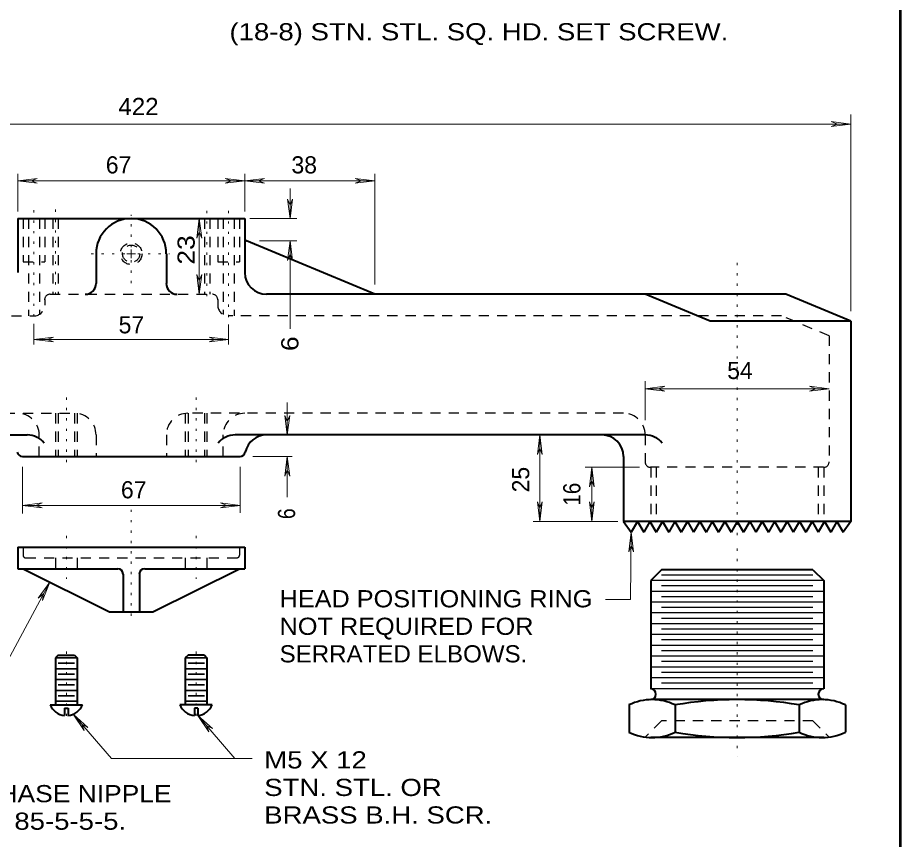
# Model space of a CAD drawing. Extents: x 312583 to 312854, y 144419 to 144597.
# Drawn here: x 312651.22 to 312690.31, y 144522.02 to 144558.42 of the extents above; entities that cross this region are included whole.
import ezdxf

# ---------------------------------------------------------------- set-up
doc = ezdxf.new("R2010")
doc.units = 0
doc.header["$LTSCALE"] = 0.3
doc.linetypes.add('DOTTED', pattern=[1.5, 0.3, -1.2])
doc.linetypes.add('SHORT_DASHED', pattern=[2.7, 1.5, -1.2])
doc.layers.add('1', color=7, linetype='Continuous', lineweight=40)
doc.layers.add('2', color=7, linetype='Continuous', lineweight=13)

msp = doc.modelspace()

# ---------------------------------------------------------------- linework, layer by layer
at = {"layer": '1', "lineweight": 53}
msp.add_line((312690.3095, 144476.2913), (312690.3095, 144585.0846), dxfattribs=at)
at = {"layer": '1', "linetype": 'DOTTED', "lineweight": 13}
for p, q in [((312651.9371, 144549.8912), (312651.9371, 144544.8619)), ((312652.8954, 144549.9219), (312652.8954, 144545.8049)), ((312659.6037, 144549.8605), (312659.6037, 144545.8049)), ((312660.5621, 144549.8605), (312660.5621, 144544.8312)), ((312683.0867, 144547.5605), (312683.0867, 144535.1559)), ((312653.3784, 144541.5959), (312653.3784, 144538.3989)), ((312659.1284, 144541.5959), (312659.1284, 144538.3989)), ((312656.2534, 144536.6279), (312656.2534, 144531.5679)), ((312653.3784, 144535.4625), (312653.3784, 144533.5612)), ((312659.1284, 144535.4625), (312659.1284, 144533.5612)), ((312683.0867, 144534.9105), (312683.0867, 144525.7029)), ((312653.3784, 144530.3489), (312653.3784, 144527.2899)), ((312659.1284, 144530.3489), (312659.1284, 144527.2899))]:
    msp.add_line(p, q, dxfattribs=at)
at = {"layer": '1'}
for p, q in [((312651.2241, 144549.5232), (312651.2241, 144547.1312)), ((312651.2241, 144549.5232), (312661.2827, 144549.5232)), ((312661.2827, 144549.5232), (312661.2827, 144547.1312)), ((312667.0327, 144546.1729), (312661.3594, 144548.5342)), ((312654.6971, 144547.9669), (312654.6971, 144546.6482)), ((312657.8097, 144547.9669), (312657.8097, 144546.6482)), ((312685.2411, 144546.1729), (312662.2411, 144546.1729)), ((312681.8831, 144544.9769), (312679.0081, 144546.1729)), ((312688.1161, 144544.9769), (312685.2411, 144546.1729)), ((312688.1161, 144544.9769), (312681.8831, 144544.9769)), ((312633.4911, 144539.9399), (312651.6457, 144539.9399)), ((312679.0081, 144539.9399), (312660.8534, 144539.9399)), ((312651.4387, 144538.9815), (312661.0681, 144538.9815)), ((312678.0497, 144538.9815), (312678.0497, 144536.1065)), ((312678.0497, 144536.1065), (312678.3947, 144535.6312)), ((312678.6707, 144536.1065), (312678.3947, 144535.6312)), ((312678.6707, 144536.1065), (312678.9467, 144535.6312)), ((312679.2227, 144536.1065), (312678.9467, 144535.6312)), ((312679.2227, 144536.1065), (312679.4987, 144535.6312)), ((312679.7747, 144536.1065), (312679.4987, 144535.6312)), ((312679.7747, 144536.1065), (312680.0507, 144535.6312)), ((312680.3267, 144536.1065), (312680.0507, 144535.6312)), ((312680.3267, 144536.1065), (312680.6027, 144535.6312)), ((312680.8787, 144536.1065), (312680.6027, 144535.6312)), ((312680.8787, 144536.1065), (312681.1547, 144535.6312)), ((312681.4307, 144536.1065), (312681.1547, 144535.6312)), ((312681.4307, 144536.1065), (312681.7067, 144535.6312)), ((312681.9827, 144536.1065), (312681.7067, 144535.6312)), ((312681.9827, 144536.1065), (312682.2587, 144535.6312)), ((312682.5347, 144536.1065), (312682.2587, 144535.6312)), ((312682.5347, 144536.1065), (312682.8107, 144535.6312)), ((312683.0867, 144536.1065), (312682.8107, 144535.6312)), ((312683.0867, 144536.1065), (312683.3627, 144535.6312)), ((312683.6387, 144536.1065), (312683.3627, 144535.6312)), ((312683.6387, 144536.1065), (312683.9147, 144535.6312)), ((312684.1907, 144536.1065), (312683.9147, 144535.6312)), ((312684.1907, 144536.1065), (312684.4667, 144535.6312)), ((312684.7427, 144536.1065), (312684.4667, 144535.6312)), ((312684.7427, 144536.1065), (312685.0187, 144535.6312)), ((312685.2947, 144536.1065), (312685.0187, 144535.6312)), ((312685.2947, 144536.1065), (312685.5707, 144535.6312)), ((312685.8467, 144536.1065), (312685.5707, 144535.6312)), ((312685.8467, 144536.1065), (312686.1227, 144535.6312)), ((312686.3987, 144536.1065), (312686.1227, 144535.6312)), ((312686.3987, 144536.1065), (312686.6747, 144535.6312)), ((312686.9507, 144536.1065), (312686.6747, 144535.6312)), ((312686.9507, 144536.1065), (312687.2267, 144535.6312)), ((312687.5027, 144536.1065), (312687.2267, 144535.6312)), ((312687.5027, 144536.1065), (312687.7787, 144535.6312)), ((312688.1161, 144536.1065), (312687.7787, 144535.6312)), ((312651.2241, 144534.9719), (312661.2827, 144534.9719)), ((312651.2241, 144534.9719), (312651.2241, 144534.0135)), ((312661.2827, 144534.9719), (312661.2827, 144534.0135)), ((312651.2241, 144534.0135), (312655.6554, 144534.0135)), ((312651.4617, 144534.0135), (312655.2951, 144532.0969)), ((312655.8931, 144533.7759), (312655.8931, 144532.0969)), ((312656.6137, 144533.7759), (312656.6137, 144532.0969)), ((312656.8514, 144534.0135), (312661.2827, 144534.0135)), ((312657.2117, 144532.0969), (312661.0451, 144534.0135)), ((312679.7287, 144533.9675), (312679.2534, 144533.4845)), ((312686.4371, 144533.9675), (312679.7287, 144533.9675)), ((312686.4371, 144533.9675), (312686.9201, 144533.4845)), ((312679.2534, 144533.4845), (312679.2534, 144528.6929)), ((312686.9201, 144533.4845), (312686.9201, 144528.6929)), ((312655.2951, 144532.0969), (312657.2117, 144532.0969)), ((312653.0181, 144530.1802), (312652.8954, 144530.0652)), ((312653.0181, 144530.1802), (312653.7387, 144530.1802)), ((312653.7387, 144530.1802), (312653.8537, 144530.0652)), ((312658.7681, 144530.1802), (312658.6454, 144530.0652)), ((312659.4887, 144530.1802), (312658.7681, 144530.1802)), ((312659.4887, 144530.1802), (312659.6037, 144530.0652)), ((312652.8954, 144530.0652), (312652.8954, 144527.9875)), ((312653.8537, 144530.0652), (312653.8537, 144527.9875)), ((312658.6454, 144530.0652), (312658.6454, 144527.9875)), ((312659.6037, 144530.0652), (312659.6037, 144527.9875)), ((312686.9201, 144528.2175), (312679.2534, 144528.2175)), ((312652.6577, 144527.9875), (312654.0991, 144527.9875)), ((312653.3017, 144527.8419), (312653.3017, 144527.5122)), ((312653.3017, 144527.8419), (312653.4551, 144527.8419)), ((312653.4551, 144527.8419), (312653.4551, 144527.5122)), ((312659.8414, 144527.9875), (312658.4077, 144527.9875)), ((312659.0517, 144527.8419), (312659.0517, 144527.5122)), ((312659.2051, 144527.8419), (312659.0517, 144527.8419)), ((312659.2051, 144527.8419), (312659.2051, 144527.5122)), ((312678.2951, 144527.9799), (312678.2951, 144526.7762)), ((312680.3344, 144527.9799), (312680.3344, 144526.7762)), ((312685.8314, 144527.9799), (312685.8314, 144526.7762)), ((312687.8784, 144527.9799), (312687.8784, 144526.7762)), ((312686.9201, 144526.5385), (312679.2534, 144526.5385))]:
    msp.add_line(p, q, dxfattribs=at)
at = {"layer": '1', "linetype": 'SHORT_DASHED', "lineweight": 25}
for p, q in [((312651.6994, 144549.5232), (312651.6994, 144545.2145)), ((312652.1824, 144549.5232), (312652.1824, 144545.2759)), ((312652.4201, 144549.5232), (312652.4201, 144547.6065)), ((312652.7804, 144549.5232), (312652.7804, 144546.1729)), ((312653.0181, 144549.5232), (312653.0181, 144546.1729)), ((312659.4887, 144549.5232), (312659.4887, 144546.1729)), ((312659.7264, 144549.5232), (312659.7264, 144546.1729)), ((312660.0867, 144549.5232), (312660.0867, 144547.6065)), ((312660.3244, 144549.5232), (312660.3244, 144545.2759)), ((312660.8074, 144549.5232), (312660.8074, 144545.2145)), ((312661.0451, 144549.5232), (312661.0451, 144547.6065)), ((312660.0867, 144547.6065), (312661.0451, 144547.6065)), ((312652.6577, 144546.1729), (312659.8491, 144546.1729)), ((312652.4201, 144545.9352), (312652.4201, 144545.6899)), ((312660.0867, 144545.9352), (312660.0867, 144545.6899)), ((312627.4574, 144545.2145), (312651.9371, 144545.2145)), ((312685.0494, 144545.2145), (312660.5621, 144545.2145)), ((312687.1577, 144544.3329), (312685.0494, 144545.2145)), ((312687.1577, 144544.3329), (312687.1577, 144538.7439)), ((312634.4494, 144540.8982), (312653.7387, 144540.8982)), ((312652.8954, 144540.8982), (312652.8954, 144538.9815)), ((312653.0181, 144540.8982), (312653.0181, 144538.9815)), ((312653.7387, 144540.8982), (312653.7387, 144538.9815)), ((312653.8537, 144540.8982), (312653.8537, 144538.9815)), ((312658.6454, 144540.8982), (312658.6454, 144538.9815)), ((312678.0497, 144540.8982), (312658.7681, 144540.8982)), ((312658.7681, 144540.8982), (312658.7681, 144538.9815)), ((312659.4887, 144540.8982), (312659.4887, 144538.9815)), ((312659.6037, 144540.8982), (312659.6037, 144538.9815)), ((312652.1747, 144538.9815), (312652.1747, 144539.9399)), ((312654.6971, 144539.9399), (312654.6971, 144538.9815)), ((312657.8097, 144539.9399), (312657.8097, 144538.9815)), ((312660.3244, 144538.9815), (312660.3244, 144539.9399)), ((312679.0081, 144539.9399), (312679.0081, 144538.7439)), ((312686.9124, 144538.5062), (312679.2457, 144538.5062)), ((312679.2534, 144538.5062), (312679.2534, 144536.1065)), ((312679.4911, 144538.5062), (312679.4911, 144536.1065)), ((312686.6747, 144538.5062), (312686.6747, 144536.1065)), ((312686.9201, 144538.5062), (312686.9201, 144536.1065)), ((312651.4617, 144534.9719), (312651.4617, 144534.6115)), ((312661.0451, 144534.9719), (312661.0451, 144534.6115)), ((312651.5844, 144534.4965), (312660.9301, 144534.4965)), ((312652.8954, 144534.4965), (312652.8954, 144534.0135)), ((312653.8537, 144534.4965), (312653.8537, 144534.0135)), ((312658.6454, 144534.4965), (312658.6454, 144534.0135)), ((312659.6037, 144534.4965), (312659.6037, 144534.0135)), ((312679.7287, 144527.2745), (312679.0157, 144526.5539)), ((312686.4371, 144527.2745), (312679.7287, 144527.2745)), ((312686.4371, 144527.2745), (312687.1577, 144526.5539))]:
    msp.add_line(p, q, dxfattribs=at)
at = {"layer": '1', "lineweight": 25}
for p, q in [((312686.4371, 144533.7299), (312679.7287, 144533.7299)), ((312686.9201, 144533.4845), (312679.2534, 144533.4845)), ((312686.4371, 144533.2469), (312679.7287, 144533.2469)), ((312686.9201, 144533.0092), (312679.2534, 144533.0092)), ((312686.9201, 144532.5262), (312679.2534, 144532.5262)), ((312686.4371, 144532.7715), (312679.7287, 144532.7715)), ((312686.4371, 144532.2885), (312679.7287, 144532.2885)), ((312686.9201, 144532.0509), (312679.2534, 144532.0509)), ((312686.4371, 144531.8132), (312679.7287, 144531.8132)), ((312686.9201, 144531.5679), (312679.2534, 144531.5679)), ((312686.4371, 144531.3302), (312679.7287, 144531.3302)), ((312686.9201, 144531.0925), (312679.2534, 144531.0925)), ((312686.9201, 144530.6095), (312679.2534, 144530.6095)), ((312686.4371, 144530.8549), (312679.7287, 144530.8549)), ((312686.9201, 144530.1342), (312679.2534, 144530.1342)), ((312686.4371, 144530.3719), (312679.7287, 144530.3719)), ((312686.4371, 144529.8965), (312679.7287, 144529.8965)), ((312686.9201, 144529.6512), (312679.2534, 144529.6512)), ((312686.4371, 144529.4135), (312679.7287, 144529.4135)), ((312686.9201, 144529.1759), (312679.2534, 144529.1759)), ((312686.9201, 144528.6929), (312679.2534, 144528.6929)), ((312686.4371, 144528.9382), (312679.7287, 144528.9382))]:
    msp.add_line(p, q, dxfattribs=at)
at = {"layer": '1', "lineweight": 35}
for p, q in [((312652.8954, 144530.0652), (312653.8537, 144530.0652)), ((312653.0181, 144529.8275), (312653.7387, 144529.8275)), ((312659.6037, 144530.0652), (312658.6454, 144530.0652)), ((312658.7681, 144529.8275), (312659.4887, 144529.8275)), ((312652.8954, 144529.5822), (312653.8537, 144529.5822)), ((312653.0181, 144529.3445), (312653.7387, 144529.3445)), ((312658.6454, 144529.5822), (312659.6037, 144529.5822)), ((312658.7681, 144529.3445), (312659.4887, 144529.3445)), ((312652.8954, 144529.1069), (312653.8537, 144529.1069)), ((312658.6454, 144529.1069), (312659.6037, 144529.1069)), ((312652.8954, 144528.6239), (312653.8537, 144528.6239)), ((312653.0181, 144528.8692), (312653.7387, 144528.8692)), ((312658.6454, 144528.6239), (312659.6037, 144528.6239)), ((312658.7681, 144528.8692), (312659.4887, 144528.8692)), ((312653.0181, 144528.3862), (312653.7387, 144528.3862)), ((312658.7681, 144528.3862), (312659.4887, 144528.3862)), ((312652.8954, 144528.1485), (312653.8537, 144528.1485)), ((312658.6454, 144528.1485), (312659.6037, 144528.1485))]:
    msp.add_line(p, q, dxfattribs=at)
at = {"layer": '1', "linetype": 'SHORT_DASHED', "lineweight": 25}
msp.add_lwpolyline([(312651.4617, 144549.5232), (312651.4617, 144547.6065), (312652.4201, 144547.6065)], dxfattribs=at)
at = {"layer": '1'}
msp.add_lwpolyline([(312688.1161, 144544.9769), (312688.1161, 144536.1065), (312678.0497, 144536.1065)], dxfattribs=at)
at = {"layer": '1', "linetype": 'SHORT_DASHED', "lineweight": 25}
for radius in [0.4792, 0.3833]:
    msp.add_circle((312656.2496, 144547.9669), radius, dxfattribs=at)
at = {"layer": '1'}
for centre, radius, start, end in [((312656.2496, 144547.9669), 1.5563, 0, 180), ((312661.4025, 144548.6447), 0.1198, 180, 247.38014), ((312662.2411, 144547.1274), 0.9583, 180, 270), ((312654.2141, 144546.6482), 0.4792, 270, 0), ((312658.2851, 144546.6482), 0.4792, 180, 270), ((312651.6457, 144538.9815), 0.9583, 38.26143, 90), ((312660.8534, 144538.9815), 0.9583, 90, 141.73857), ((312662.2411, 144538.9815), 0.9583, 90, 168.46304), ((312677.0914, 144538.9815), 0.9583, 0, 90), ((312679.0081, 144538.9815), 0.9583, 38.26143, 90), ((312651.4356, 144539.2211), 0.2396, 191.53696, 270), ((312661.0674, 144539.2211), 0.2396, 270, 348.46304), ((312655.6497, 144533.774), 0.2396, 0, 90), ((312656.8495, 144533.774), 0.2396, 90, 180), ((312679.2496, 144528.4514), 0.2396, 270, 90), ((312686.9162, 144528.4514), 0.2396, 90, 270), ((312679.3128, 144525.8993), 2.3144, 63.80664, 116.19336), ((312683.081, 144512.1802), 16.0335, 80.12254, 99.87746), ((312686.853, 144525.8993), 2.3144, 63.80664, 116.19336), ((312653.3765, 144528.287), 0.7786, 202.61961, 264.2087), ((312653.3765, 144528.287), 0.7786, 275.51058, 337.3804), ((312659.1227, 144528.287), 0.7786, 202.6196, 264.48942), ((312659.1227, 144528.287), 0.7786, 275.7913, 337.38039), ((312679.3128, 144528.8491), 2.3144, 243.80664, 296.19336), ((312683.081, 144542.5682), 16.0335, 260.12254, 279.87746), ((312686.853, 144528.8491), 2.3144, 243.80664, 296.19336)]:
    msp.add_arc(centre, radius, start, end, dxfattribs=at)
at = {"layer": '1', "linetype": 'SHORT_DASHED', "lineweight": 25}
for centre, radius, start, end in [((312652.6558, 144545.9294), 0.2396, 90, 180), ((312659.8433, 144545.9294), 0.2396, 0, 90), ((312651.9371, 144545.6899), 0.4792, 270, 0), ((312660.5621, 144545.6899), 0.4792, 180, 270), ((312651.2164, 144539.9399), 0.9583, 0, 90), ((312653.7349, 144539.9399), 0.9583, 0, 90), ((312658.7642, 144539.9399), 0.9583, 90, 180), ((312661.2827, 144539.9399), 0.9583, 90, 180), ((312678.0497, 144539.9399), 0.9583, 0, 90), ((312679.2477, 144538.7419), 0.2396, 180, 270), ((312686.9143, 144538.7419), 0.2396, 270, 0), ((312651.5815, 144534.6125), 0.1198, 180, 270), ((312660.9253, 144534.6125), 0.1198, 270, 0)]:
    msp.add_arc(centre, radius, start, end, dxfattribs=at)
at = {"layer": '2'}
for p, q in [((312688.1161, 144545.4215), (312688.1161, 144554.1309)), ((312624.3907, 144553.7092), (312688.1161, 144553.7092)), ((312687.2497, 144553.8165), (312687.5257, 144553.7092)), ((312688.1161, 144553.7092), (312687.2497, 144553.8165)), ((312687.2497, 144553.6019), (312687.5257, 144553.7092)), ((312688.1161, 144553.7092), (312687.2497, 144553.6019)), ((312651.2241, 144549.8375), (312651.2241, 144551.5089)), ((312651.2241, 144551.1945), (312652.0904, 144551.3019)), ((312652.0904, 144551.3019), (312651.8144, 144551.1945)), ((312660.4164, 144551.3019), (312660.6924, 144551.1945)), ((312661.2827, 144551.1945), (312660.4164, 144551.3019)), ((312661.2827, 144549.8375), (312661.2827, 144551.5089)), ((312661.2827, 144551.1945), (312662.1491, 144551.3019)), ((312662.1491, 144551.3019), (312661.8731, 144551.1945)), ((312666.1664, 144551.3019), (312666.4424, 144551.1945)), ((312667.0327, 144551.1945), (312666.1664, 144551.3019)), ((312667.0327, 144546.6022), (312667.0327, 144551.5089)), ((312651.2241, 144551.1945), (312652.0904, 144551.0872)), ((312652.0904, 144551.0872), (312651.8144, 144551.1945)), ((312660.4164, 144551.0872), (312660.6924, 144551.1945)), ((312661.2827, 144551.1945), (312660.4164, 144551.0872)), ((312661.2827, 144551.1945), (312662.1491, 144551.0872)), ((312662.1491, 144551.0872), (312661.8731, 144551.1945)), ((312663.2837, 144549.5232), (312663.2837, 144550.8572)), ((312666.1664, 144551.0872), (312666.4424, 144551.1945)), ((312667.0327, 144551.1945), (312666.1664, 144551.0872)), ((312663.1764, 144550.3895), (312663.2837, 144550.1135)), ((312663.2837, 144549.5232), (312663.1764, 144550.3895)), ((312663.3911, 144550.3895), (312663.2837, 144550.1135)), ((312663.2837, 144549.5232), (312663.3911, 144550.3895)), ((312659.2664, 144549.5232), (312659.1591, 144548.6569)), ((312659.2664, 144546.1729), (312659.2664, 144549.5232)), ((312659.2664, 144549.5232), (312659.3737, 144548.6569)), ((312661.4974, 144549.5232), (312663.5827, 144549.5232)), ((312659.1591, 144548.6569), (312659.2664, 144548.9329)), ((312659.3737, 144548.6569), (312659.2664, 144548.9329)), ((312661.9344, 144548.5342), (312663.5827, 144548.5342)), ((312663.2837, 144548.5342), (312663.1764, 144547.6679)), ((312663.2837, 144544.6395), (312663.2837, 144548.5342)), ((312663.2837, 144548.5342), (312663.3911, 144547.6679)), ((312656.2534, 144547.9669), (312656.2534, 144548.1585)), ((312656.2534, 144547.9669), (312656.0617, 144547.9669)), ((312656.2534, 144547.9669), (312656.2534, 144547.7752)), ((312656.2534, 144547.9669), (312656.4451, 144547.9669)), ((312663.1764, 144547.6679), (312663.2837, 144547.9439)), ((312663.3911, 144547.6679), (312663.2837, 144547.9439)), ((312659.1591, 144547.0392), (312659.2664, 144546.7632)), ((312659.2664, 144546.1729), (312659.1591, 144547.0392)), ((312659.3737, 144547.0392), (312659.2664, 144546.7632)), ((312659.2664, 144546.1729), (312659.3737, 144547.0392)), ((312651.9371, 144544.8619), (312651.9371, 144543.9419)), ((312660.5621, 144544.8312), (312660.5621, 144543.9419)), ((312651.9371, 144544.1642), (312652.8034, 144544.2715)), ((312652.8034, 144544.2715), (312652.5274, 144544.1642)), ((312659.6957, 144544.2715), (312659.9717, 144544.1642)), ((312660.5621, 144544.1642), (312659.6957, 144544.2715)), ((312651.9371, 144544.1642), (312660.5621, 144544.1642)), ((312651.9371, 144544.1642), (312652.8034, 144544.0569)), ((312652.8034, 144544.0569), (312652.5274, 144544.1642)), ((312659.6957, 144544.0569), (312659.9717, 144544.1642)), ((312660.5621, 144544.1642), (312659.6957, 144544.0569)), ((312679.0081, 144540.5992), (312679.0081, 144542.3242)), ((312679.0081, 144541.9869), (312679.8744, 144542.0942)), ((312687.1577, 144541.9869), (312679.0081, 144541.9869)), ((312679.0081, 144541.9869), (312679.8744, 144541.8795)), ((312679.8744, 144542.0942), (312679.5984, 144541.9869)), ((312679.8744, 144541.8795), (312679.5984, 144541.9869)), ((312686.2914, 144542.0942), (312686.5674, 144541.9869)), ((312687.1577, 144541.9869), (312686.2914, 144542.0942)), ((312686.2914, 144541.8795), (312686.5674, 144541.9869)), ((312687.1577, 144541.9869), (312686.2914, 144541.8795)), ((312663.1611, 144541.3812), (312663.1611, 144539.9399)), ((312663.0537, 144540.8062), (312663.1611, 144540.5302)), ((312663.1611, 144539.9399), (312663.0537, 144540.8062)), ((312663.2684, 144540.8062), (312663.1611, 144540.5302)), ((312663.1611, 144539.9399), (312663.2684, 144540.8062)), ((312674.3467, 144539.9399), (312674.2394, 144539.0735)), ((312674.3467, 144536.1065), (312674.3467, 144539.9399)), ((312674.3467, 144539.9399), (312674.4541, 144539.0735)), ((312674.2394, 144539.0735), (312674.3467, 144539.3495)), ((312674.4541, 144539.0735), (312674.3467, 144539.3495)), ((312661.6354, 144538.9815), (312663.3757, 144538.9815)), ((312663.1611, 144538.9815), (312663.0537, 144538.1152)), ((312663.1611, 144538.9815), (312663.1611, 144537.1875)), ((312663.1611, 144538.9815), (312663.2684, 144538.1152)), ((312651.4387, 144538.5292), (312651.4387, 144536.4515)), ((312661.0681, 144538.5292), (312661.0681, 144536.4899)), ((312663.0537, 144538.1152), (312663.1611, 144538.3912)), ((312663.2684, 144538.1152), (312663.1611, 144538.3912)), ((312678.7627, 144538.5062), (312676.3554, 144538.5062)), ((312676.6467, 144538.5062), (312676.5394, 144537.6399)), ((312676.6467, 144536.1065), (312676.6467, 144538.5062)), ((312676.6467, 144538.5062), (312676.7541, 144537.6399)), ((312676.5394, 144537.6399), (312676.6467, 144537.9159)), ((312676.7541, 144537.6399), (312676.6467, 144537.9159)), ((312651.4387, 144536.8195), (312652.3051, 144536.9269)), ((312651.4387, 144536.8195), (312661.0681, 144536.8195)), ((312651.4387, 144536.8195), (312652.3051, 144536.7122)), ((312652.3051, 144536.9269), (312652.0291, 144536.8195)), ((312652.3051, 144536.7122), (312652.0291, 144536.8195)), ((312660.2017, 144536.9269), (312660.4777, 144536.8195)), ((312661.0681, 144536.8195), (312660.2017, 144536.9269)), ((312660.2017, 144536.7122), (312660.4777, 144536.8195)), ((312661.0681, 144536.8195), (312660.2017, 144536.7122)), ((312674.2394, 144536.9729), (312674.3467, 144536.6969)), ((312674.3467, 144536.1065), (312674.2394, 144536.9729)), ((312674.4541, 144536.9729), (312674.3467, 144536.6969)), ((312674.3467, 144536.1065), (312674.4541, 144536.9729)), ((312676.5394, 144536.9729), (312676.6467, 144536.6969)), ((312676.6467, 144536.1065), (312676.5394, 144536.9729)), ((312676.7541, 144536.9729), (312676.6467, 144536.6969)), ((312676.6467, 144536.1065), (312676.7541, 144536.9729)), ((312677.8044, 144536.1065), (312674.0554, 144536.1065)), ((312678.3947, 144535.6312), (312678.2797, 144534.7649)), ((312678.3947, 144535.6312), (312678.4944, 144534.7649)), ((312678.2797, 144534.7649), (312678.3871, 144535.0409)), ((312678.4944, 144534.7649), (312678.3871, 144535.0409)), ((312652.6424, 144533.4232), (312652.1364, 144532.7102)), ((312652.6424, 144533.4232), (312652.3281, 144532.6105)), ((312652.1364, 144532.7102), (312652.3664, 144532.9019)), ((312652.3281, 144532.6105), (312652.3664, 144532.9019)), ((312653.6774, 144527.5735), (312654.1604, 144526.8452)), ((312653.6774, 144527.5735), (312654.3291, 144526.9832)), ((312659.2051, 144527.5122), (312660.8457, 144525.6109)), ((312659.2051, 144527.5122), (312659.6881, 144526.7915)), ((312659.2051, 144527.5122), (312659.8491, 144526.9295)), ((312654.1604, 144526.8452), (312654.0684, 144527.1212)), ((312654.3291, 144526.9832), (312654.0684, 144527.1212)), ((312659.6881, 144526.7915), (312659.5884, 144527.0675)), ((312659.8491, 144526.9295), (312659.5884, 144527.0675))]:
    msp.add_line(p, q, dxfattribs=at)
at = {"layer": '2', "linetype": 'DOTTED'}
for p, q in [((312656.2534, 144548.2582), (312656.2534, 144549.6919)), ((312655.9621, 144547.9669), (312654.3827, 144547.9669)), ((312656.5371, 144547.9669), (312657.9401, 144547.9669)), ((312656.2534, 144547.6832), (312656.2534, 144546.3569))]:
    msp.add_line(p, q, dxfattribs=at)
at = {"layer": '2'}
for points in [[(312651.2241, 144551.1945), (312661.2827, 144551.1945), (312667.0327, 144551.1945)], [(312678.3947, 144535.6312), (312678.3564, 144532.6489), (312677.2524, 144532.6489)], [(312648.8627, 144527.8802), (312649.6601, 144527.8802), (312652.6424, 144533.4232)], [(312653.6774, 144527.5735), (312655.3717, 144525.6109), (312661.6047, 144525.6109)]]:
    msp.add_lwpolyline(points, dxfattribs=at)

# ---------------------------------------------------------------- texts
for s, width, p in [('(18-8) STN. STL. SQ. HD. SET SCREW.', 1.2, (312660.6004, 144557.4189)), ('422', 1.05, (312655.683, 144554.1083)), ('HEAD POSITIONING RING', 1.1, (312662.8218, 144532.3023)), ('NOT REQUIRED FOR', 1.1, (312662.8218, 144531.0823)), ('SERRATED ELBOWS.', 1.05, (312662.8218, 144529.8623)), ('M5 X 12', 1.2, (312662.1414, 144525.1647)), ('STN. STL. OR', 1.2, (312662.1414, 144523.9447)), ('STANDARD 40 MM CHASE NIPPLE', 1.15, (312638.8787, 144523.6693)), ('BRASS B.H. SCR.', 1.2, (312662.1414, 144522.7247)), ('MATERIAL: BRONZE 85-5-5-5.', 1.2, (312638.8787, 144522.4493))]:
    msp.add_text(s, height=0.76, dxfattribs=dict(at, width=width)).set_placement(p)
for s, p in [('67', (312655.1256, 144551.5228)), ('38', (312663.3473, 144551.5227)), ('57', (312655.6939, 144544.4392)), ('54', (312682.6419, 144542.4158)), ('67', (312655.7956, 144537.1301))]:
    msp.add_text(s, height=0.76, dxfattribs=at).set_placement(p)
for s, width, p in [('23 ', 1.15, (312659.0616, 144547.4828)), ('6 ', 1.15, (312663.6537, 144543.655)), ('16', 0.9, (312676.1415, 144536.8037)), ('6', 0.85, (312663.5076, 144536.2078))]:
    msp.add_text(s, height=0.76, rotation=90, dxfattribs=dict(at, width=width)).set_placement(p)
msp.add_text('25', height=0.76, rotation=90, dxfattribs=at).set_placement((312673.8769, 144537.3943))

doc.saveas('drawing.dxf')
